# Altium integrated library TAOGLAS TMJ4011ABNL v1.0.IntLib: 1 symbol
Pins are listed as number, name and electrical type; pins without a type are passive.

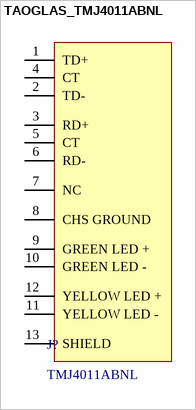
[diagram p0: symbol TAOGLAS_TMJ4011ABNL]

## TAOGLAS_TMJ4011ABNL
designator J?, comment TMJ4011ABNL
RJ45 connector with integrated magnetics 10/100Base-T Single Port Tab-DOWN with right angle THT mount and LEDs; ComponentLibStatus: Created; MFG: Taoglas; Temp_High: +85C; Temp_Low: -40C
footprint TAOGLAS_TMJ4011ABNL (RJ45 connector with integrated magnetics 10/100Base-T Single Port Tab-DOWN with right angle THT mount and LEDs)
pins: 1 TD+, 2 TD-, 3 RD+, 4 CT, 5 CT, 6 RD-, 7 NC, 8 CHS GROUND, 9 GREEN LED +, 10 GREEN LED -, 11 YELLOW LED -, 12 YELLOW LED +, 13 SHIELD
